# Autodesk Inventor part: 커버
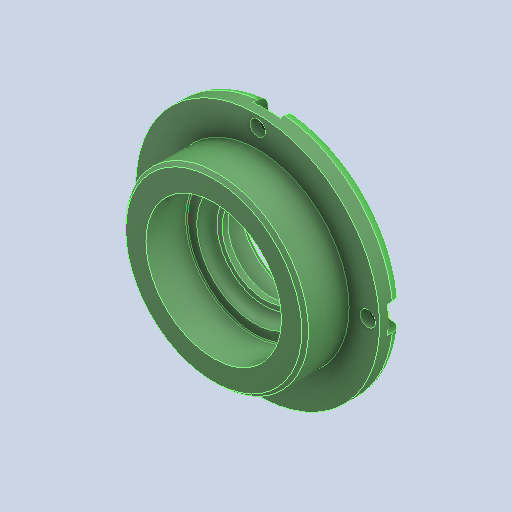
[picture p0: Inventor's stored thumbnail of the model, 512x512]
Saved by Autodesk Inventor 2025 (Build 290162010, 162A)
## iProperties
Created: 2024-07
Part Number: 커버
Material: 강철, 연강
Document SubType Name: Modeling
Designer: 학생
Density: 7.86 g/cm^3
Appearance: 기본값
Company: 한국ATC센터
Author: jhkim
Revision Number: 1
Sending System: Autodesk Inventor 2025
Preprocessor: ST-DEVELOPER v20
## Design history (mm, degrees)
feature "솔리드1"
node "솔리드2"
